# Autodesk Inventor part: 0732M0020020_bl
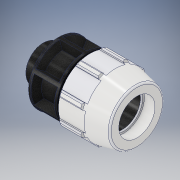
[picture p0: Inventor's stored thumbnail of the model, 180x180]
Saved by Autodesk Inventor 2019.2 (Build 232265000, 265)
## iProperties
Created: 2017-02
Part Number: 0732M0020020_bl
Material: PVC-Piping
Description: PLASSON SHOULDERED ADAPTOR 2''-2''
Document SubType Name: Modeling
Designer: KIM
Mass: 92.6774 g
Surface Area: 199.44 cm^2
Volume: 66.1981 cm^3
Density: 1.4 g/cm^3
Appearance: PTFE
Author: KIM
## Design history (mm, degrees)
derived "0732M.ipt"
feature "Solid1::0732M.ipt" dims "ScaleForDerivedMember" = 10
tag "TaggingFeature1"
body "Solid1"
other parameters: "d2" = 60.1 [user parameter], "d4" = 22.27943 [user parameter], "d5" = 38.989 [user parameter], "d7" = 113.03 [user parameter], "d9" = 22.27943 [user parameter], "d11" = 4.45589 [user parameter], "d12" = 90.424 [user parameter], "d13" = 120 deg [user parameter], "d14" = 90.15 [user parameter], "d15" = 12 deg [user parameter], "d16" = 101.727 [user parameter], "d18" = 3.005 [user parameter], "d19" = 35 deg [user parameter], "d20" = 17.5 deg [user parameter], "d21" = 105.1179 [user parameter], "d23" = 0 [user parameter], "d25" = 360 deg [user parameter], "d27" = 2.2606 [user parameter], "d34" = 5.6515 [user parameter], "d36" = 0 [user parameter], "d42" = 38.989 [user parameter], "d43" = 3.3909 [user parameter], "d46" = 1.803 [user parameter], "d51" = 155.956 [user parameter], "d53" = 1.202 [user parameter], "d55" = 360 deg [user parameter], "d58" = 47.6912 [user parameter], "d62" = 122.936 [user parameter], "d63" = 16.002 [user parameter], "d64" = 59.614 [user parameter], "d65" = 4.45589 [user parameter], "d66" = 38.989 [user parameter], "d67" = 75.125 [user parameter], "d68" = 70 deg [user parameter], "d69" = 1.27 [user parameter], "d" = 60.1 [user parameter], "E_" = 113.03 [user parameter], "H_" = 155.956 [user parameter], "l_" = 122.936 [user parameter], "L" = 16.002 [user parameter], "B" = 59.614 [user parameter]
